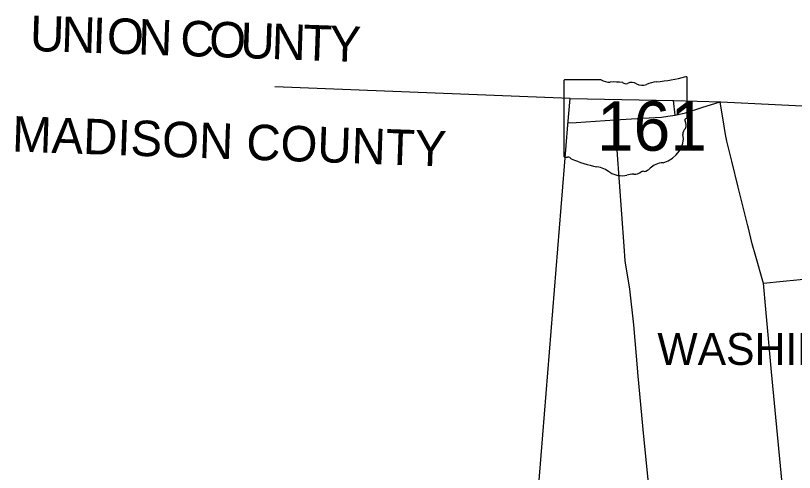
# Model space of a CAD drawing. Extents: x 1755200 to 1902939, y 644115 to 788070.
# Drawn here: x 1755200 to 1777186, y 757899 to 770779 of the extents above; entities that cross this region are included whole.
import ezdxf

# ---------------------------------------------------------------- set-up
doc = ezdxf.new("R2010")
doc.units = 0
for name, color, linetype in [('GM_X_Adjacent_County', 7, 'Continuous'), ('GM_X_Adjacent_County_Text', 7, 'Continuous'), ('GM_X_City_Street', 7, 'Continuous'), ('GM_X_County', 7, 'Continuous'), ('GM_X_County_Road', 7, 'Continuous'), ('GM_X_State_Route', 7, 'Continuous'), ('GM_X_State_Shield', 7, 'Continuous'), ('GM_X_Township_Road', 7, 'Continuous'), ('GM_X_Township_Text', 7, 'Continuous')]:
    doc.layers.add(name, color=color, linetype=linetype)

msp = doc.modelspace()

# ---------------------------------------------------------------- linework, layer by layer
at = {"layer": 'GM_X_Adjacent_County'}
msp.add_line((1770854, 768445), (1762519, 768766), dxfattribs=at)
at = {"layer": 'GM_X_City_Street'}
for points in [[(1775876, 764825), (1775871, 764848), (1775850, 764928)], [(1776894, 757007), (1776536, 760730), (1776379, 762498), (1776312, 763238), (1776297, 763289)], [(1773148, 756519), (1773062, 757592), (1772919, 759113), (1772768, 760711), (1772766, 760732)]]:
    msp.add_lwpolyline(points, dxfattribs=at)
at = {"layer": 'GM_X_County'}
msp.add_lwpolyline([(1769900, 756629), (1770794, 767696), (1770854, 768445), (1773771, 768383), (1775112, 768352), (1778179, 768197)], dxfattribs=at)
at = {"layer": 'GM_X_County_Road'}
for points in [[(1775850, 764928), (1775594, 765946), (1775415, 766673), (1775278, 767240), (1775242, 767424), (1775205, 767658), (1775094, 768346)], [(1772766, 760732), (1772657, 762055), (1772537, 763066), (1772406, 763865), (1772376, 764274), (1772178, 766985), (1772115, 767838)], [(1776297, 763289), (1776096, 763986), (1775996, 764347), (1775876, 764825)], [(1776312, 763238), (1776864, 763293), (1777637, 763368), (1778352, 763436), (1778667, 763465), (1779104, 763498)]]:
    msp.add_lwpolyline(points, dxfattribs=at)
at = {"layer": 'GM_X_State_Route'}
msp.add_lwpolyline([(1770782, 767754), (1771024, 767766), (1772115, 767838), (1772909, 767883), (1773429, 767916), (1773615, 767939), (1773818, 767968), (1774109, 768040), (1774573, 768184), (1775094, 768346), (1775112, 768352)], dxfattribs=at)
at = {"layer": 'GM_X_State_Shield'}
for p, q in [((1770680, 768934), (1770680, 766820)), ((1771733, 768970), (1770714, 768970)), ((1774160, 767917), (1774160, 769022)), ((1774160, 767917), (1774160, 767917))]:
    msp.add_line(p, q, dxfattribs=at)
for centre, major_axis, start_param, end_param in [((1772920, 771851), (3691, 0), 4.814394, 5.042369), ((1774121, 769027), (38.7, 0), 6.141152, 7.989035), ((1770719, 768938), (40.3, 0), 1.712693, 3.28349), ((1771976, 769215), (391, 0), 4.042523, 4.731795), ((1772106, 767784), (1404, 0), 1.404758, 1.657858), ((1772424, 768949), (113, 0), 3.836095, 5.185415), ((1772590, 768705), (235, 0), 0.950623, 2.079405), ((1772893, 769040), (282, 0), 4.081561, 5.145723), ((1773391, 768325), (743, 0), 1.699011, 2.107814), ((1774151, 767836), (60, 0), 1.883978, 3.671073), ((1773770, 767696), (360, 0), 5.934695, 6.695948), ((1774119, 767913), (41.5, 0), 5.05454, 6.418171), ((1774299, 767454), (262, 0), 2.387724, 3.262537), ((1773127, 767314), (923, 0), 5.101752, 6.440018), ((1770720, 766816), (40.7, 0), 3.00124, 4.508301), ((1770726, 767032), (310, 0), 4.665946, 4.897461), ((1770790, 766698), (112, 0), 0.519207, 1.627899), ((1772203, 768597), (2665, 0), 4.195997, 4.488961), ((1773516, 766227), (506, 0), 1.647645, 2.488434), ((1771408, 765871), (834, 0), 0.823519, 1.323587), ((1772876, 766616), (298, 0), 4.937069, 5.64225), ((1772310, 766688), (529, 0), 4.026481, 4.996735), ((1772616, 765957), (435, 0), 1.495662, 1.94098), ((1772654, 766530), (282, 0), 4.691044, 5.507374), ((1772909, 766325), (79.4, 0), 1.147584, 2.315152)]:
    msp.add_ellipse(centre, major_axis=major_axis, ratio=0.8, start_param=start_param, end_param=end_param, dxfattribs=at)
at = {"layer": 'GM_X_Township_Road'}
msp.add_lwpolyline([(1773818, 767968), (1773771, 768383)], dxfattribs=at)

# ---------------------------------------------------------------- texts
at = {"layer": 'GM_X_Adjacent_County_Text'}
for s, rotation, p in [('U', 358.1705, (1755595, 769783)), ('N', 358.1702, (1756478, 769755)), ('I', 358.1643, (1757360, 769727)), ('O', 358.1324, (1757766, 769714)), ('N', 358.0802, (1758648, 769685)), ('C', 358.0225, (1759836, 769645)), ('O', 358.018, (1760650, 769617)), ('U', 358.0179, (1761532, 769586)), ('N', 358.0179, (1762415, 769556)), ('T', 358.0181, (1763297, 769525)), ('Y', 358.0181, (1764043, 769499)), ('MADISON COUNTY', 358.0066, (1755091, 766949))]:
    msp.add_text(s, height=1000, rotation=rotation, dxfattribs=at).set_placement(p)
at = {"layer": 'GM_X_State_Shield'}
msp.add_text('161', height=1392.2, dxfattribs=at).set_placement((1771610, 766969))
at = {"layer": 'GM_X_Township_Text'}
msp.add_text('WASHINGTON', height=900, rotation=0, dxfattribs=at).set_placement((1773318, 760930))

doc.saveas('drawing.dxf')
